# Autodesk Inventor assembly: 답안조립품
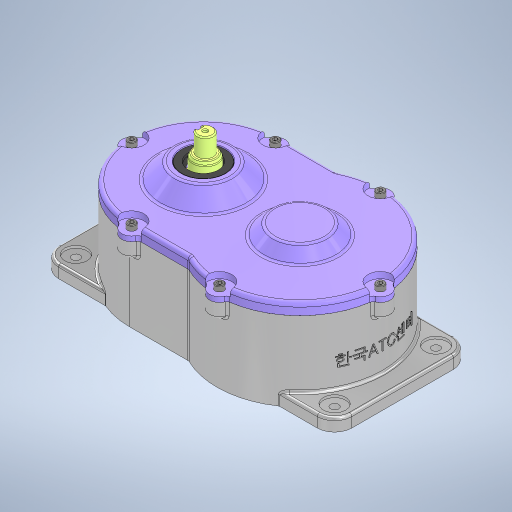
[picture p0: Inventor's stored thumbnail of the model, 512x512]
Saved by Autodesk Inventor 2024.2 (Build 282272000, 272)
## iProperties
Created: 2025-09
Part Number: 답안조립품
Document SubType Name: Assembly
Designer: home
Author: home
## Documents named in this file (19)
- C:\Users\home\Desktop\750903V1008\답안조립품.iam
- C:\Users\home\Desktop\750903V1008\본체.ipt
- C:\Users\home\Desktop\750903V1008\슬롯 축\슬롯 축.ipt
- C:\Users\home\Desktop\750903V1008\깊은 홈 볼 베어링 6904\깊은 홈 볼 베어링 6904.ipt
- C:\Users\home\Desktop\750903V1008\6각 구멍붙이 볼트 M6x12\6각 구멍붙이 볼트 M6x12.ipt
- C:\Users\home\Desktop\750903V1008\어댑터\어댑터.ipt
- C:\Users\home\Desktop\750903V1008\평행 키 6x6x14\평행 키 6x6x14.ipt
- C:\Users\home\Desktop\750903V1008\슬롯\슬롯.ipt
- C:\Users\home\Desktop\750903V1008\칼라\칼라.ipt
- C:\Users\home\Desktop\750903V1008\커버\커버.ipt
- C:\Users\home\Desktop\750903V1008\오일 실 20 35 8\오일 실 20 35 8.ipt
- C:\Users\home\Desktop\750903V1008\스러스트 볼 베어링 51102\스러스트 볼 베어링 51102.ipt
- C:\Users\home\Desktop\750903V1008\구동 축\구동 축.ipt
- C:\Users\home\Desktop\750903V1008\구동 휠\구동 휠.ipt
- C:\Users\home\Desktop\750903V1008\캠 플로워\캠 플로워.ipt
- C:\Users\home\Desktop\750903V1008\평 와셔 M3\평 와셔 M3.ipt
- C:\Users\home\Desktop\750903V1008\스프링 와셔 M3\스프링 와셔 M3.ipt
- C:\Users\home\Desktop\750903V1008\육각 너트 M3\육각 너트 M3.ipt
- C:\Users\home\Desktop\750903V1008\6각 구멍붙이 볼트 M4x10\6각 구멍붙이 볼트 M4x10.ipt
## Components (9 placed, 4 different names)
1. 6각 구멍붙이 볼트 M6x12:1
2. 구동 축:1
3. 구동 휠:1
4. 6각 구멍붙이 볼트 M4x10:1
5. 6각 구멍붙이 볼트 M4x10:2
6. 6각 구멍붙이 볼트 M4x10:3
7. 6각 구멍붙이 볼트 M4x10:4
8. 6각 구멍붙이 볼트 M4x10:5
9. 6각 구멍붙이 볼트 M4x10:6
